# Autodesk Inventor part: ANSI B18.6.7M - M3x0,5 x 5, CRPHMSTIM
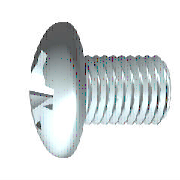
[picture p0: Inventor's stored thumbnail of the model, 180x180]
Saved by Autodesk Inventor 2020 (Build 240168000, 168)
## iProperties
Created: 2019-01
Part Number: ANSI B18.6.7M - M3x0,5 x 5, CRPHMSTIM
Material: Acier, doux
Description: Vis à tête tronconique à empreinte cruciforme - Type IA - Métrique
Document SubType Name: Modeling
Standard: ANSI B18.6.7M
Designer: bruno
Standard Revision: 2005
Standards Organization: ANSI
Language: fr-FR
Size Designation: M3x0,5 x 5
Categories: <MemberInstance><Categories><Category DisplayName="Visserie" InternalName="e4da775c-781d-43d5-af7c-5136215cf5a6" Mnemonic="FSTN"><Category DisplayName="Vis" Int
Density: 7.85 g/cm^3
Appearance: Semi-poli
IsCustomPart: 0
Author: bruno
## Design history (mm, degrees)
body "Solid1"
workplane "Work Plane3"
sketch "Esquisse4"
  geometry: L1 (-9, 0)-(9, 0) reference; L2 (0, -9)-(0, 9) reference; L3 (0, 0)-(6.428, 6.428); L4 (0, 0)-(6.428, -6.428); L5 (0, 0)-(-6.428, 6.428); L6 (0, 0)-(-6.428, -6.428); L7 (1.011, 1.011)-(0, 0.183); L8 (-1.011, 1.011)-(-0.182, 0); L9 (-1.011, -1.011)-(0, -0.183); L10 (1.011, -1.011)-(0.182, 0); L11 (1.011, 1.011)-(0.182, 0); L12 (-1.011, 1.011)-(0, 0.183); L13 (-1.011, -1.011)-(-0.182, 0); L14 (1.011, -1.011)-(0, -0.183); C1 r 2.8 at (0, 0) reference; A1 r 0.182 centre (0, 0) between (0, 0.183) and (-0.182, 0); A2 r 1.43 centre (0, 0) between (1.011, 1.011) and (1.011, -1.011); 1 further point
  constraints: 24 end point, 10 point on line, 7 point on circle, 3 perpendicular, 3 symmetric about line, 2 centre point, 2 coincident, 3 other
  dimensions: "d11" = 0.365 diameter of A1 (= 0.5 x SBR); "d14" = 45 deg angle of L3 L1; "d35" = 1.01116 distance from line of L1 L7.start (= 0.353553 x SDM)
extrude "Coupe en étoile" cut sketch "Esquisse4" distance "d12" = 2.4 (= KOH); taper "d13" = -10 deg
sketch "Esquisse2"
  geometry: L1 (-4.704, 0)-(8.625, 0) reference; L2 (0, -4.704)-(0, 8.625) reference; L3 (0, 1.43)-(0, 0); L4 (0, 0)-(1.43, 0); L5 (0, 0)-(6.721, 6.721); L6 (0.365, 1.383)-(0.213, 0.683); L7 (1.383, 0.365)-(0.683, 0.213); L8 (1.383, -0.365)-(0.683, -0.213); L9 (0.365, -1.383)-(0.213, -0.683); L10 (-0.365, 1.383)-(-0.213, 0.683); L11 (-1.383, 0.365)-(-0.683, 0.213); L12 (-0.365, -1.383)-(-0.213, -0.683); L13 (-1.383, -0.365)-(-0.683, -0.213); C1 r 2.8 at (0, 0) reference; A1 r 0.572 centre (0, 0) between (0.572, 0) and (0, 0.572); A2 r 0.181 centre (0.389, 0.644) between (0.213, 0.683) and (0.517, 0.517); A3 r 0.181 centre (0.644, 0.389) between (0.517, 0.517) and (0.683, 0.213); A4 r 1.43 centre (0, 0) between (1.43, 0) and (1.383, 0.365); A5 r 1.43 centre (0, 0) between (0.365, 1.383) and (0, 1.43); A6 r 1.43 centre (0, 0) between (1.383, 0.365) and (0.365, 1.383); A7 r 1.43 centre (0, 0) between (0, -1.43) and (0.365, -1.383); A8 r 1.43 centre (0, 0) between (0.365, -1.383) and (1.383, -0.365); A9 r 1.43 centre (0, 0) between (1.383, -0.365) and (1.43, 0); A10 r 0.181 centre (0.389, -0.644) between (0.517, -0.517) and (0.213, -0.683); A11 r 0.181 centre (0.644, -0.389) between (0.683, -0.213) and (0.517, -0.517); A12 r 0.181 centre (-0.389, 0.644) between (-0.517, 0.517) and (-0.213, 0.683); A13 r 0.181 centre (-0.644, 0.389) between (-0.683, 0.213) and (-0.517, 0.517); A14 r 1.43 centre (0, 0) between (-1.383, 0.365) and (-1.43, 0); A15 r 1.43 centre (0, 0) between (-0.365, 1.383) and (-1.383, 0.365); A16 r 1.43 centre (0, 0) between (0, 1.43) and (-0.365, 1.383); A17 r 1.43 centre (0, 0) between (-1.43, 0) and (-1.383, -0.365); A18 r 1.43 centre (0, 0) between (-1.383, -0.365) and (-0.365, -1.383); A19 r 1.43 centre (0, 0) between (-0.365, -1.383) and (0, -1.43); A20 r 0.181 centre (-0.644, -0.389) between (-0.517, -0.517) and (-0.683, -0.213); A21 r 0.181 centre (-0.389, -0.644) between (-0.213, -0.683) and (-0.517, -0.517); A22 r 0.715 centre (0, 0) between (0.715, 0) and (0, 0.715)
  constraints: 46 point on circle, 25 symmetric about line, 22 centre point, 22 end point, 6 tangent, 4 coincident, 3 collinear, 3 point on line, 1 midpoint, 1 perpendicular, 22 other
  dimensions: "d4" = 45 deg angle of L5 L4; "d5" = 1.144 diameter of A1 (= 0.4 x SDM); "d6" = 2.86 diameter of A6 (= SDM); "d7" = 0.365 distance from line of L6.start L3 (= 0.5 x SBR); "d20" = 1.43 diameter of A22 (= 0.5 x SDM)
extrude "Rainure" join sketch "Esquisse2" taper "d21" = 5 deg; stored distance "d54" = 10
revolve "Coupe" stored, may be unused: angle "d56" = 90 deg
revolve "Corps" stored, may be unused: angle "d18" = 90 deg
node "IDS_WORKPLANE{1}"
sketch "Esquisse1"
  geometry: L1 (5, 0)-(5, 1.5); L2 (5, 1.5)-(0.5, 1.5); L3 (3.962, 5.08)-(3.962, 5.08); L4 (-2.4, 0)-(-2.4, 2.8); L5 (-2.217, 1.339)-(-0.672, 0.569); L6 (-0.672, 0.569)-(-0.37, 0); L7 (-0.37, 0)-(5, 0); L8 (-4.131, 0)-(6.522, 0) reference; L9 (0, -1.016)-(0, 6.096) reference; L10 (-2.217, 1.339)-(-2.4, 1.43); L11 (-1.542, 2.8)-(-2.4, 2.8); L12 (-1.542, 2.8)-(0, 2.8); L13 (0, 2.8)-(0, 1.5); L14 (0, 1.5)-(0.193, 1.5); L15 (0.193, 1.5)-(0.5, 1.5); L16 (0.5, 1.5)-(0, 1.5); A1 r 5 centre (2.6, 0) between (-1.542, 2.8) and (-2.4, 0)
  constraints: 28 end point, 5 collinear, 5 point on line, 4 point on circle, 2 parallel, 2 perpendicular, 1 centre point, 1 horizontal, 1 tangent
  dimensions: "d1" = 3 diameter of L2 L7 (= GD); "d2" = 2.03 distance from line of L6.end L4 (= STI); "d16" = 2.86 diameter of L10.end L7 (= SDM); "d17" = 62 deg angle of L6 L7; "d19" = 26.5 deg angle of L5 L7; "d23" = 5.6 diameter of L12.end L7 (= KOD); "d24" = 0 deg angle of L12 L7 (computed from KEWI); "d25" = 2.4 distance between parallel lines of L4 L13 (= KOH); "d26" = 5 radius of A1 (= KR); "d28" = 3 diameter of L14 L7 (= BDM); "d29" = 4.5 distance of L1.end L2.end (= GEL); "d30" = 0.30673 distance of L14.end L2.end (= GAL); "d31" = 5 distance between parallel lines of L13 L1 (= NLG)
fillet "Congé1" dims "d32" = 1 (= RR)
fillet "Congé2" dims "d22" = 0.146 (= 0.2 x SBR)
feature "Filetage" dims "d8" = 4.5 (= GEL), "d9" = 0
chamfer "Chanfrein1" distance "d36" = 0.44 (= -0.5 x SPD + 0.5 x GD); stored, may be unused: second distance "d37" = 0.30683 (computed from GUL), angle "d81" = 45 deg
fillet "Congé3" dims "d84" = 0.1 (= R)
other parameters: "GD" = 3 (= NND) [user parameter; used in 2 equation terms], "NLG" = 5 [user parameter; used in 1 equation term], "GEL" = 4.5 [user parameter; used in 2 equation terms], "KOD" = 5.6 [user parameter; used in 1 equation term], "KOH" = 2.4 [user parameter; used in 3 equation terms], "SDM" = 2.86 [user parameter; used in 5 equation terms], "STI" = 2.03 [user parameter; used in 1 equation term], "SBR" = 0.73 [user parameter; used in 3 equation terms], "KEWI" = 0 [user parameter; used in 1 equation term], "d3" = -2.4 (= -KOH), "d10" = 0, "KR" = 5 [user parameter; used in 1 equation term], "BDM" = 3 (= NND) [user parameter; used in 1 equation term], "GAL" = 0.30673 (= 0.61345 x PTC) [user parameter; used in 1 equation term], "GUL" = 0.30673 (= 0.61345 x PTC) [user parameter; used in 1 equation term], "RR" = 1 [user parameter; used in 1 equation term], "SPD" = 2.12 [user parameter; used in 1 equation term], "d82" = 0, "d83" = 0, "R" = 0.1 [user parameter; used in 1 equation term], "PTC" = 0.5 [user parameter; used in 4 equation terms], "THREADDIA" = 3 [user parameter; used in 1 equation term], "TOA" = 30 deg [user parameter], "NND" = 3 [user parameter; used in 2 equation terms], "GD1" = 2.38655 (= THREADDIA - 1.2269 x PTC) [user parameter]
